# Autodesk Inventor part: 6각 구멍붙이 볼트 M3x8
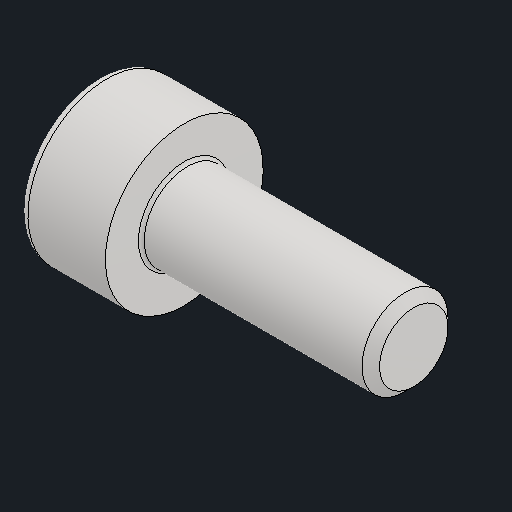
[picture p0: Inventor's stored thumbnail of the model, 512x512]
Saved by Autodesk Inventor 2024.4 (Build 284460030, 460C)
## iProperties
Created: 2026-08
Part Number: 6각 구멍붙이 볼트 M3x8
Material: 스테인리스강
Description: 6각 소켓 머리 캡 나사
Document SubType Name: Modeling
Designer: user
Density: 8.08 g/cm^3
Appearance: 기본값
Author: jhkim
Sending System: Autodesk Inventor 2027
Preprocessor: ST-DEVELOPER v20.1
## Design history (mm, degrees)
feature "Solid1"
node "솔리드1"
